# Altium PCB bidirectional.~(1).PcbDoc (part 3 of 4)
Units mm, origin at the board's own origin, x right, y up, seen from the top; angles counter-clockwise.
Board outline 190.5 x 127 mm, 6 copper layers (Top Layer, MidLayer1, MidLayer2, Mid-Layer 3, Mid-Layer 4, Bottom Layer), stack 2.997 mm thick; 416 components, 178 nets, 1084 pads, 2010 vias.
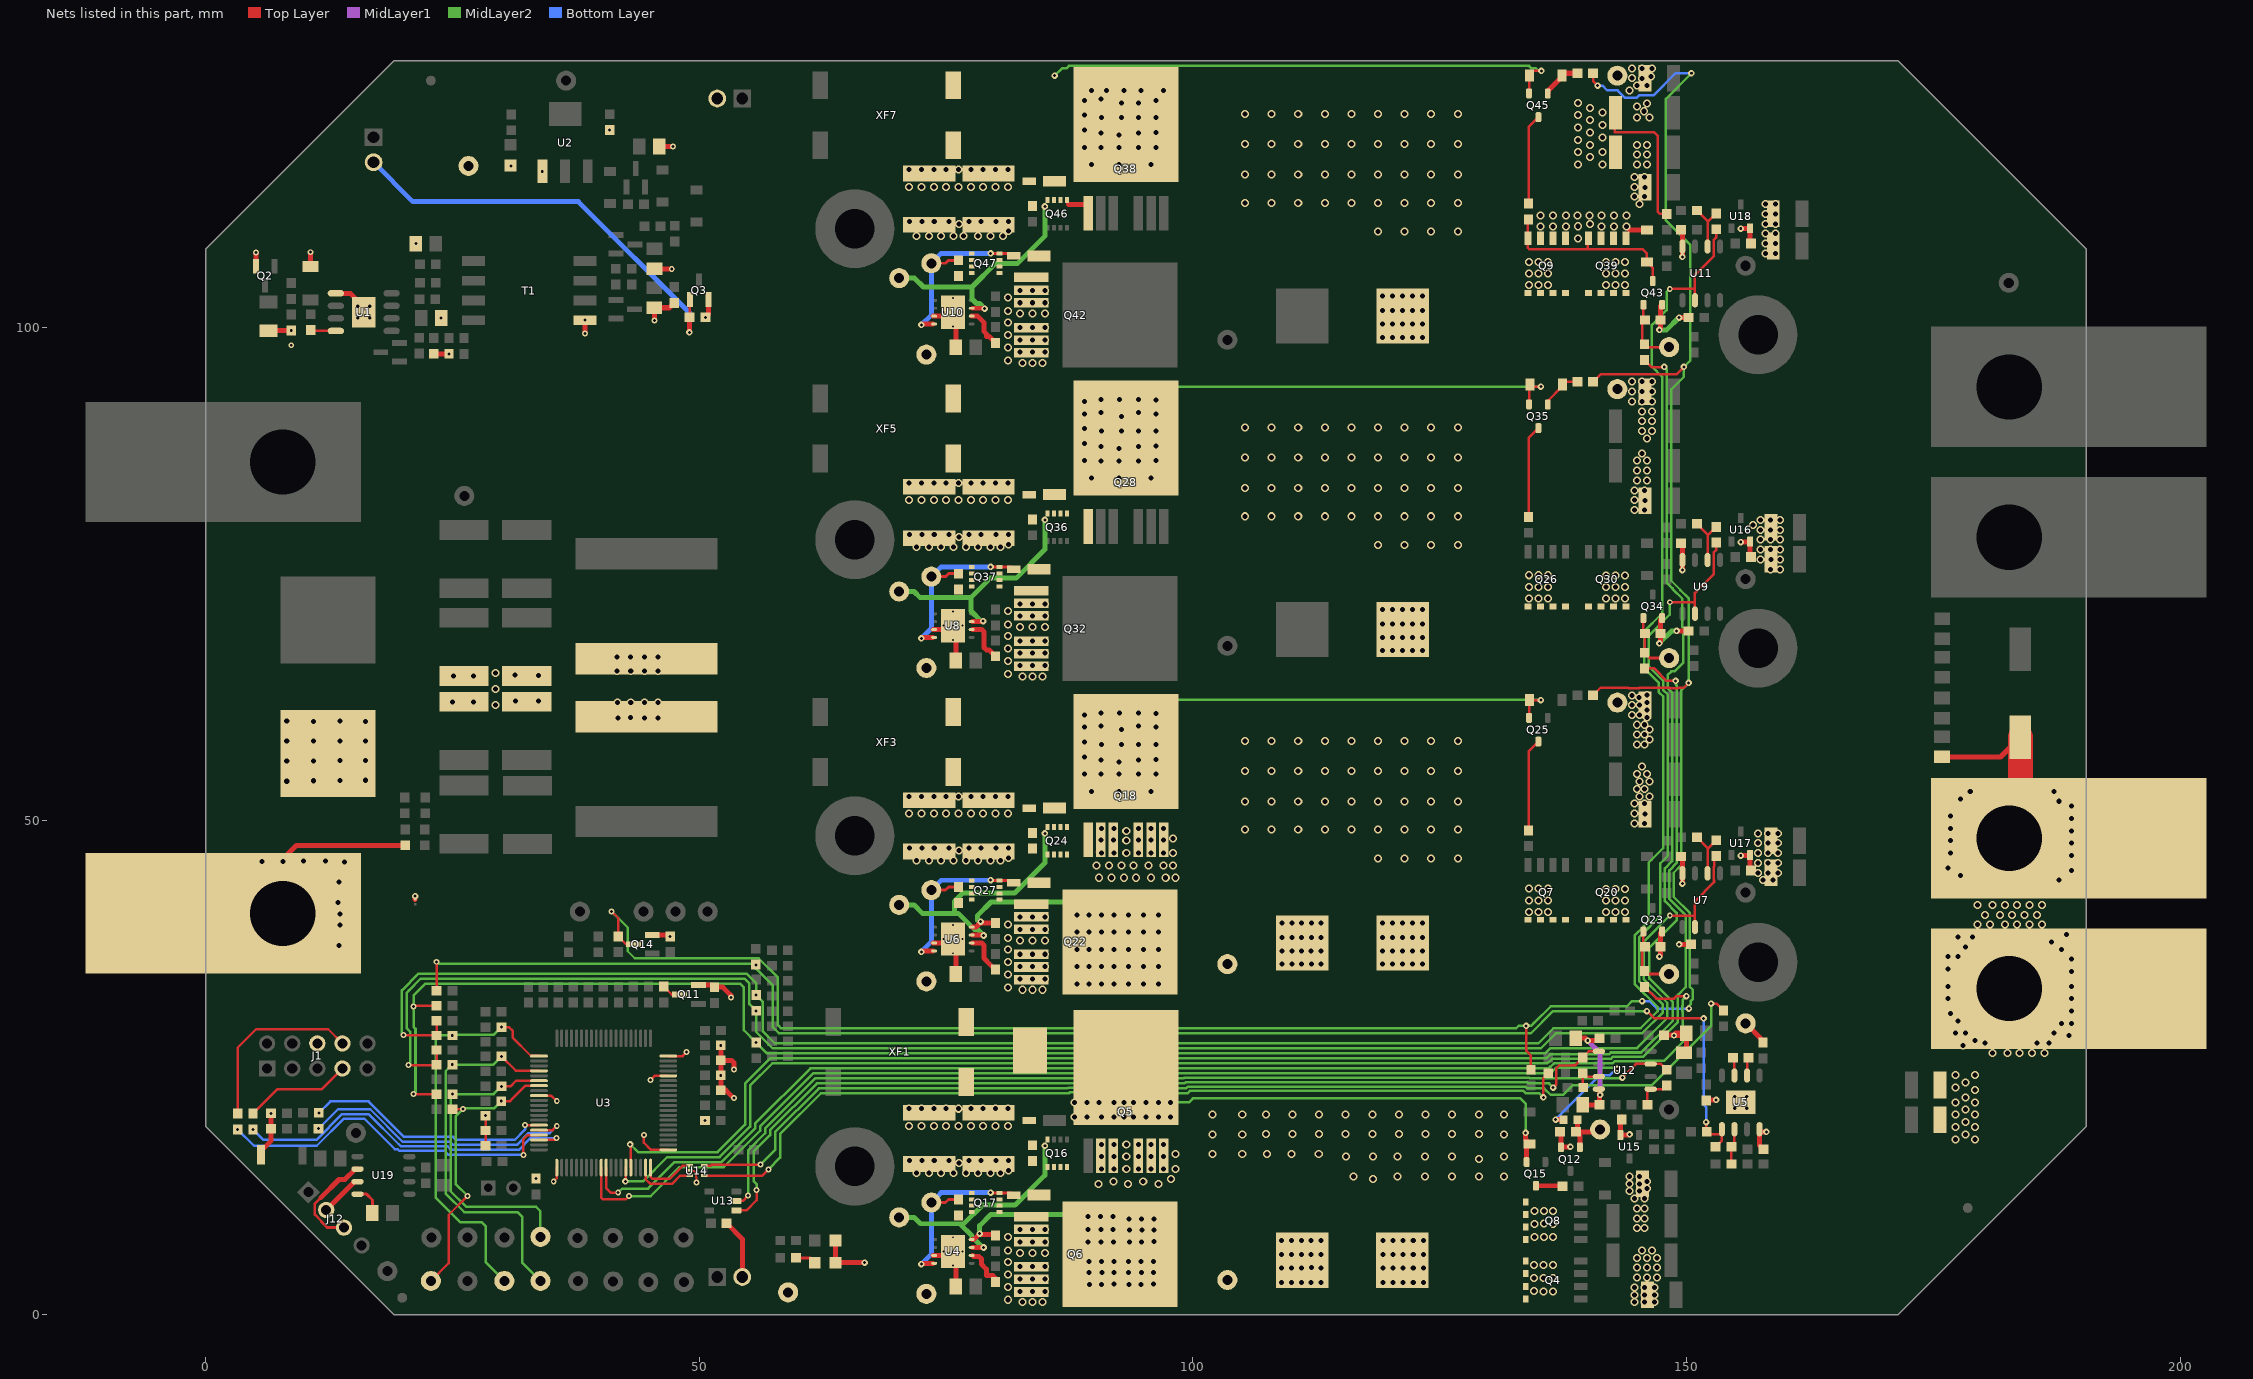
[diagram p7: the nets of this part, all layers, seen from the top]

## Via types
v1: diameter 0.813, hole 0.508, Top Layer to Bottom Layer, 1661 vias
v2: diameter 0.6, hole 0.3, Top Layer to Bottom Layer, 178 vias
v3: diameter 0.66, hole 0.3, Top Layer to Bottom Layer, 84 vias
v4: diameter 0.66, hole 0.3, Top Layer to Bottom Layer, tented both sides, 35 vias
v5: diameter 0.5, hole 0.2, Top Layer to Bottom Layer, 20 vias
v6: diameter 0.813, hole 0.508, Top Layer to Bottom Layer, tented both sides, 10 vias
v7: diameter 0.66, hole 0.33, Top Layer to Bottom Layer, tented top, 8 vias
v8: diameter 0.6, hole 0.3, Top Layer to Bottom Layer, tented both sides, 7 vias
v9: diameter 0.813, hole 0.508, Top Layer to Bottom Layer, tented top, 5 vias
v10: diameter 0.864, hole 0.406, Top Layer to Bottom Layer, 2 vias

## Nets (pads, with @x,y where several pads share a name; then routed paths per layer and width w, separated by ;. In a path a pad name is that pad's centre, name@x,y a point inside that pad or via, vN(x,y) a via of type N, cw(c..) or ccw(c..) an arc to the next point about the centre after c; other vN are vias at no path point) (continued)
NetD14_1: D14.1 Q9.4 Q39.4 Q43.3 R94.2 | length 19.4
  Top Layer w0.254: R94.2@134,110.95 133.939,110.889 Q9.4@133.939,109.041 133.939,108.068 134.092,107.916 140,107.916 ; Q39.4@140.086,109.041 140,108.955 140,107.916 ; Q43.3@146.588,104.7 146.588,106.024 D14.1@146,106.612 146,107.5 145.584,107.916 140,107.916
NetD14_2: D14.2 Q9.1 Q9.2 Q9.3 Q39.1 Q39.2 Q39.3 R90.1 R95.1 R103.1 | length 17.1
  Top Layer w0.25: R95.1@142.75,121.45 142.75,119.75 146.75,119.75 147.07,119.43 147.07,111.73 147.3,111.5 R103.1@148,111.5
  Top Layer w0.254: v1@135.209,111.091 v1@135.235,111.091
  Top Layer w0.508: v1(143.922,110.202) 144.236,109.887 D14.2@146,109.887
  other v1: 139,109 135.209,110.202 136.505,110.202 137.775,110.202 141.382,110.202 142.652,110.202 139,110.25 140.25,110.5 135.209,111.345 136.479,111.345 137.775,111.345 138.969,111.345 140.162,111.345 141.382,111.345 142.652,111.345 143.922,111.345 139,116.5 141.5,116.5 140.25,117.25 139,117.75 141.5,117.75 140.25,118.5 139,119 141.5,119.25 140.25,119.75 139,120.25 141.5,120.5 140.25,121 139,121.5 141.5,121.75 140.25,122.25 139,122.75
NetD15_2: D15.2 Q45.1 R101.1 | length 4.1
  Top Layer w0.508: Q45.1@135.95,123.7 135.95,123.95 137.388,125.388 D15.2@137.388,125.5 137.637,125.75 R101.1@138.95,125.75
NetD16_1: D16.1 R16.1 | length 2.1
  Top Layer w0.3: R16.1@59.8,5.75 61.2,5.75 D16.1@61.7,5.25
NetD18_2: D18.2 Q35.1 R82.1 | length 4.2
  Top Layer w0.254: Q35.1@135.95,92.2 135.95,92.562 137.388,94 137.887,94.5 R82.1@138.95,94.5
NetD19_1: D19.1 Q6.1 Q17.1 Q17.2 Q17.3 | length 0
  Top Layer w0.5: Q6.1@84.694,9.906 Q6.1@84.7,9.912
NetD20_1: D20.1 Q18.1 Q24.1 Q24.2 Q24.3
NetD21_1: D21.1 Q22.1 Q27.1 Q27.2 Q27.3
NetD22_1: D22.1 Q28.1 Q36.1 Q36.2 Q36.3 | length 0.9
  Top Layer w0.5: Q28.1@89.366,80.7 89.408,80.658 Q28.1@89.408,79.836
NetD23_1: D23.1 Q32.1 Q37.1 Q37.2 Q37.3
NetD24_1: D24.1 Q38.1 Q46.1 Q46.2 Q46.3 | length 2.7
  Top Layer w0.5: 87.4,112.45 89.05,112.45 89.408,112.092 Q38.1@89.408,111.586
NetD25_1: D25.1 Q42.1 Q47.1 Q47.2 Q47.3
NetJ1_7: J1.7 R26.1 | length 11
  Top Layer w0.254: R26.1@4.781,20.362 7.218,22.8 11.71,22.8 J1.7@13.84,24.93
NetJ1_8: J1.8 R24.1 | length 18.6
  Top Layer w0.254: R24.1@3.231,20.362 3.231,27.031 5.1,28.9 12.41,28.9 J1.8@13.84,27.47
NetJ12_2: J12.2 U19.7 | length 4.4
  Top Layer w0.5: J12.2@12.202,10.598 15.069,13.465 U19.7@15.375,13.465
NetJ12_3: J12.3 U19.6 | length 10.4
  Top Layer w0.25: 11.686,11.872 11.053,11.239 11.053,10.122 11.726,9.449
  Top Layer w0.3: 11.708,9.431 12.338,8.802 J12.3@13.998,8.802
  Top Layer w0.5: 11.686,11.872 13.5,13.686 14.086,13.686 15.135,14.735 U19.6@15.375,14.735
NetL1_2: L1.2 L2.1
  other v1: 41.758,60.452 44.425,60.452 45.796,60.452 43.028,60.477 41.707,62.027 43.053,62.027 44.425,62.027 45.796,62.027 41.656,65.176 43.053,65.176 44.425,65.176 45.796,65.176 41.656,66.599 43.028,66.599 44.425,66.599 45.796,66.599
NetL3_2: L3.2 Q4.5 Q4.6 Q4.7 Q4.8 Q8.5 Q8.6 Q8.7 Q8.8
  other v1: 135.535,2.358 136.5,2.358 134.57,2.384 119.25,3.25 120.291,3.25 121.307,3.25 122.323,3.25 123.339,3.25 134.57,3.679 135.535,3.679 136.5,3.679 119.275,4.698 120.291,4.698 121.307,4.698 122.323,4.698 123.339,4.698 134.57,5 135.535,5 136.5,5 119.275,6.069 120.291,6.069 121.307,6.069 122.323,6.069 123.339,6.069 119.275,7.492 120.291,7.492 121.307,7.492 122.323,7.492 123.339,7.492 136.5,9.179 135.56,9.205 134.62,10.5 135.56,10.5 136.5,10.5
  other v9: 134.62,7.858 135.56,7.858 136.5,7.858 134.62,9.179
NetL4_2: L4.2 Q7.5 Q7.6 Q7.7 Q7.8 Q20.5 Q20.6 Q20.7 Q20.8
  other v1: 119.211,35.5 120.227,35.5 121.243,35.5 122.234,35.5 123.25,35.5 119.211,36.846 120.227,36.846 121.243,36.846 122.234,36.846 123.25,36.846 119.211,38.218 120.227,38.218 121.243,38.218 122.234,38.218 123.25,38.218 119.211,39.666 120.227,39.666 121.243,39.666 122.234,39.666 123.25,39.666 134.066,40.784 135.032,40.784 142.804,40.784 143.769,40.784 134.066,41.952 135.032,41.952 135.997,41.952 141.839,41.952 142.804,41.952 143.769,41.952 141.839,43.12 142.804,43.12 143.769,43.12 134.066,43.146 135.032,43.146 135.997,43.146
  other v6: 135.997,40.784 141.839,40.784
NetL5_2: L5.2 Q26.5 Q26.6 Q26.7 Q26.8 Q30.5 Q30.6 Q30.7 Q30.8
  other v1: 119.211,67.25 120.227,67.25 121.243,67.25 122.234,67.25 123.25,67.25 119.211,68.596 120.227,68.596 121.243,68.596 122.234,68.596 123.25,68.596 119.211,69.968 120.227,69.968 121.243,69.968 122.234,69.968 123.25,69.968 119.211,71.416 120.227,71.416 121.243,71.416 122.234,71.416 123.25,71.416 134.066,72.534 135.032,72.534 142.804,72.534 143.769,72.534 134.066,73.702 135.032,73.702 135.997,73.702 141.839,73.702 142.804,73.702 143.769,73.702 141.839,74.87 142.804,74.87 143.769,74.87 134.066,74.896 135.032,74.896 135.997,74.896
  other v6: 135.997,72.534 141.839,72.534
NetL6_2: L6.2 Q9.5 Q9.6 Q9.7 Q9.8 Q39.5 Q39.6 Q39.7 Q39.8
  other v1: 119.211,99 120.227,99 121.243,99 122.234,99 123.25,99 119.211,100.346 120.227,100.346 121.243,100.346 122.234,100.346 123.25,100.346 119.211,101.718 120.227,101.718 121.243,101.718 122.234,101.718 123.25,101.718 119.211,103.166 120.227,103.166 121.243,103.166 122.234,103.166 123.25,103.166 134.066,104.284 135.032,104.284 142.804,104.284 143.769,104.284 134.066,105.452 135.032,105.452 135.997,105.452 141.839,105.452 142.804,105.452 143.769,105.452 141.839,106.62 142.804,106.62 143.769,106.62 134.066,106.646 135.032,106.646 135.997,106.646
  other v6: 135.997,104.284 141.839,104.284
NetQ11_3: Q11.3 R35.1 | length 1.9
  Top Layer w0.254: R35.1@46.406,33.223 47.206,32.423 Q11.3@48.006,32.423
NetQ15_3: Q15.3 R34.1 | length 2.7
  Top Layer w0.5: Q15.3@134.75,13.05 137.4,13.05 R34.1@137.45,13
NetQ25_3: Q25.3 R56.1 | length 9.4
  Top Layer w0.254: R56.1@134,49.05 134,57.05 Q25.3@135,58.05
NetQ35_3: Q35.3 R75.1 | length 9.4
  Top Layer w0.254: R75.1@134,80.8 134,88.8 Q35.3@135,89.8
NetQ45_3: Q45.3 R94.1 | length 9.3
  Top Layer w0.254: R94.1@134,112.55 134,120.3 Q45.3@135,121.3 ; Q45.3@134.875,121.425 Q45.3@135,121.55
NetR4_2: R4.2 U1.4 | length 2.5
  Top Layer w0.254: R4.2@10.706,99.644 U1.4@13.208,99.644
NetR20_2: R20.2 U4.2 | length 4.4
  Top Layer w0.5: U4.2@77.686,5.993 77.783,5.896 78.316,5.896 78.579,5.633 78.579,5.099 79.076,4.603 79.076,3.939 79.74,3.939 80,3.679 R20.2@80,3.288
NetR21_2: R21.2 U6.2 | length 4.2
  Top Layer w0.5: U6.2@77.686,37.643 78.455,37.643 78.477,37.621 78.629,37.621 78.838,37.412 78.838,36.1 79.076,35.862 79.076,35.852 79.99,34.938 R21.2@80,34.938
NetR22_2: R22.2 U8.2 | length 4.4
  Top Layer w0.5: U8.2@77.686,69.393 78.607,69.393 78.838,69.162 78.838,67.577 79.076,67.339 79.349,67.339 R22.2@80,66.688
NetR23_2: R23.2 U10.2 | length 4.2
  Top Layer w0.5: U10.2@77.592,101.142 78.196,101.142 78.859,100.479 78.859,99.579 79.076,99.362 79.076,99.089 79.349,99.089 R23.2@80,98.438
NetR43_2: R43.2@13.616,15.8 U19.5 | length 1.8
  Top Layer w0.5: R43.2@13.616,15.8 13.821,16.005 U19.5@15.375,16.005
NetR43_2: R43.2@154.55,15.25 R44.1 U5.2 | length 3.4
  Top Layer w0.254: R43.2@154.55,15.25 154.55,16.75 154.865,17.065 U5.2@154.865,18.525
NetR44_2: R44.2 R45.1 R47.2 R120.1 U5.1 | length 154
  Top Layer w0.254: R45.1@23.381,32.791 23.381,35.725 v2(23.393,35.738) ; v3(146,30.75) 146.75,30 v3(151.75,30) ; v3(152,19.5) 152,18.3 152.05,18.25 153.32,18.25 U5.1@153.595,18.525 ; R44.2@152.95,16.75 R44.2@153.075,16.875 ; R44.2@152.95,17 153.595,17.645 U5.1@153.595,18.525 ; U5.1@153.595,18.775 U5.1@153.595,18.525
  MidLayer2 w0.254: v2(23.393,35.738) 23.571,35.56 55.575,35.56 v2(55.728,35.408) 55.728,35.048 57.455,33.321 57.455,29.105 58.061,28.499 134.25,28.499 136.501,30.75 v3(146,30.75)
  Bottom Layer w0.254: v3(151.75,30) 151.75,21.25 152,21 v3(152,19.5)
NetR60_1: R60.1 R62.2 R64.1 R66.2 U7.6 | length 172.4
  Top Layer w0.254: v2(21.057,22.327) R60.1@23.381,22.327 ; v2(21.057,31.191) 21.158,31.293 R64.1@23.381,31.293 ; v2(148.311,40.411) 150.761,40.411 150.865,40.308 ; U7.6@150.865,39.25 150.865,40.308 ; R62.2@153,46.45 152.8,46.25 152.8,45.405 152.779,45.384 152.779,44.016 152.8,43.995 152.8,43.8 150.865,41.865 150.865,40.308
  MidLayer2 w0.254: v2(21.057,22.327) 21.247,22.517 21.247,28.943 21.057,29.134 v2(21.057,31.191) 21.057,32.309 22.276,33.528 54.127,33.528 54.508,33.147 54.508,28.803 v2(55.753,27.559) 56.845,26.467 135.687,26.467 136.22,27 145,27 148.057,30.057 148.057,31.584 145.656,33.985 145.656,37.757 v2(148.311,40.411)
NetR61_2: R61.2 R62.1 U7.2 | length 5.3
  Top Layer w0.25: R61.2@151.05,48.35 152.135,47.265 ; U7.2@152.135,44.7 152.135,47.265 ; R62.1@153,48.05 152.215,47.265 152.135,47.265
NetR79_1: R79.1 R81.2 R83.1 R85.2 U9.6 | length 203
  Top Layer w0.254: v2@20.549,25.273 R79.1@23.381,25.273 ; R79.1@23.381,25.298 R83.1@23.381,26.797 ; v2(148.311,72.161) 150.761,72.161 150.865,72.058 ; U9.6@150.865,71 150.865,72.058 ; R81.2@152.8,78 R81.2@153,78.2 153,77.45 152.779,77.229 152.779,75.029 150.865,73.115 150.865,72.058
  MidLayer2 w0.254: v2(20.549,25.298) 20.701,25.451 20.701,28.651 20.371,28.981 20.371,32.61 20.574,32.814 20.574,32.831 21.779,34.036 54.585,34.036 55.067,33.553 55.067,31.458 v2(55.753,30.772) 55.753,28.651 57.429,26.975 135.25,26.975 136.775,28.5 145.5,28.5 147.604,30.604 147.604,31.396 145.203,33.797 145.203,38.202 146.135,39.134 ; 146.15,39.149 146.135,39.134 ; 146.614,39.642 146.135,39.164 146.135,39.134 ; 146.635,39.642 147.358,40.365 147.358,45.723 148.104,46.469 148.104,62.812 147.641,63.276 147.641,64.209 146.156,65.693 146.156,68.75 148.311,70.905 v2(148.311,72.161)
NetR80_2: R80.2 R81.1 U9.2 | length 5.3
  Top Layer w0.25: R80.2@151.05,80.1 152.135,79.015 ; U9.2@152.135,76.45 152.135,79.015 ; R81.1@153,79.8 152.215,79.015 152.135,79.015
NetR98_1: R98.1 R100.2 R102.1 R104.2 U11.6 | length 233.2
  Top Layer w0.254: v2@20.041,28.27 R98.1@23.381,28.27 ; R98.1@23.406,28.143 R102.1@23.406,29.642 ; v2(148.311,103.911) 150.761,103.911 150.865,103.808 ; U11.6@150.865,102.75 150.865,103.808 ; R100.2@152.8,109.75 R100.2@153,109.95 153,109.105 152.779,108.884 152.779,107.229 150.865,105.315 150.865,103.808
  MidLayer2 w0.254: v2(20.015,28.321) 19.863,28.473 19.863,32.838 21.568,34.544 54.795,34.544 55.753,33.586 v2(55.753,32.36) 56.439,31.674 56.439,28.684 57.64,27.483 135,27.483 136.517,29 145.346,29 147.096,30.75 147.096,31.154 144.75,33.5 144.75,38.389 145.682,39.321 145.682,39.351 146.203,39.872 146.203,40.188 146.182,40.209 146.182,45.781 147.651,47.25 147.651,62.625 147.188,63.088 147.188,64.021 145.703,65.505 145.703,69.203 147.547,71.047 147.547,94.998 146.5,96.045 146.5,100.25 148,101.75 148,103.601 v2(148.311,103.911)
NetR99_2: R99.2 R100.1 U11.2 | length 5.3
  Top Layer w0.25: R99.2@151.05,111.85 152.135,110.765 ; U11.2@152.135,108.2 152.135,110.765 ; R100.1@153,111.55 152.215,110.765 152.135,110.765
NetR109_1: R109.1 U14.4 | length 93.8
  Top Layer w0.254: U14.4@50.499,14.08 56.385,14.08 57,14.695 v2(57,14.7) ; v3(135.5,22) 135.5,23.95 R109.1@136,24.45
  MidLayer2 w0.254: v2(57,14.7) 58.191,15.891 58.191,18.291 62.303,22.403 87.441,22.403 87.572,22.533 88.428,22.533 88.559,22.403 88.691,22.403 88.822,22.533 89.678,22.533 89.809,22.403 89.941,22.403 90.072,22.533 90.928,22.533 91.059,22.403 91.441,22.403 91.572,22.533 92.428,22.533 92.5,22.461 92.572,22.533 93.428,22.533 93.5,22.461 93.572,22.533 94.428,22.533 94.559,22.403 94.691,22.403 94.822,22.533 95.678,22.533 95.809,22.403 95.941,22.403 96.072,22.533 96.928,22.533 97.059,22.403 97.191,22.403 97.322,22.533 98.178,22.533 98.309,22.403 99.442,22.403 99.688,22.649 133.486,22.649 133.732,22.403 135.097,22.403 v3(135.5,22)
NetR111_2: R111.2 R112.2 U12.3 | length 2.7
  Top Layer w0.254: 139.5,23.874 139.5,23.05 R111.2@139.55,23 ; R112.2@139.5,24.45 139.835,24.115 U12.3@141.125,24.115
NetR112_1: R112.1 U12.1 U13.1 | length 99.2
  Top Layer w0.2: 137.134,25.232 137.151,25.249 137.801,25.249 137.802,25.25 138.356,25.25
  Top Layer w0.25: v3(136.5,23) 136.799,23.299 136.799,24.932 137.117,25.25 ; R112.1@139.5,26.05 140.105,26.655 U12.1@141.125,26.655
  Top Layer w0.254: U13.1@53.618,10.556 54.778,10.556 55.8,11.579 v2(55.8,12.6) ; 138.356,25.25 138.7,25.25 R112.1@139.5,26.05
  MidLayer2 w0.25: 134.75,23.419 136.081,23.419 v3(136.5,23)
  MidLayer2 w0.254: v2(55.8,12.6) 55.8,13.212 55.5,13.512 55.5,16.5 57.175,18.175 57.175,18.675 61.919,23.419 87.176,23.419 87.197,23.439 88.803,23.439 90.053,23.439 91.303,23.439 92.803,23.439 93.803,23.439 94.803,23.439 96.053,23.439 97.303,23.439 98.553,23.439 98.574,23.419 99.176,23.419 99.312,23.555 133.862,23.555 133.998,23.419 134.75,23.419
NetR113_1: R113.1 U14.6 | length 113.6
  Top Layer w0.254: U14.6@50.499,15.08 51.173,15.08 51.293,15.2 v2(56.2,15.2) ; v3(152.5,31.5) 153.05,31.5 R113.1@153.75,30.8
  MidLayer2 w0.254: v2(56.2,15.2) 57.683,16.683 57.683,18.483 62.111,22.911 87.309,22.911 87.384,22.986 88.616,22.986 88.625,22.977 88.634,22.986 89.866,22.986 89.875,22.977 89.884,22.986 91.116,22.986 91.191,22.911 91.309,22.911 91.384,22.986 92.616,22.986 93.616,22.986 94.616,22.986 94.625,22.977 94.634,22.986 95.866,22.986 95.875,22.977 95.884,22.986 97.116,22.986 97.125,22.977 97.134,22.986 98.366,22.986 98.441,22.911 99.309,22.911 99.5,23.102 133.674,23.102 133.865,22.911 135.589,22.911 136.25,22.25 137.5,22.25 138.5,23.25 146.5,23.25 152.5,29.25 v3(152.5,31.5)
NetR115_2: R115.2 R116.2 U12.5 | length 3.5
  Top Layer w0.254: R115.2@146.05,21.25 146.05,22.52 U12.5@146.375,22.845 147.645,22.845 R116.2@148,23.2
NetR116_1: R116.1 U12.7 U13.2 | length 103.4
  Top Layer w0.254: U13.2@53.618,11.506 54.407,11.506 v2(54.94,12.04) ; v3(143.5,24) 144.885,25.385 U12.7@146.375,25.385 147.415,25.385 R116.1@148,24.8
  MidLayer2 w0.254: v2(54.94,12.04) 54.94,16.64 56.667,18.367 56.667,18.867 61.727,23.927 99.044,23.927 99.125,24.008 134.049,24.008 134.13,23.927 143.427,23.927 v3(143.5,24)
NetR121_1: R121.1 U5.6 | length 1.8
  Top Layer w0.254: U5.6@156.135,24.225 156.135,25.835 R121.1@156.3,26
NetR121_2: R121.2 U5.7 | length 1.8
  Top Layer w0.254: R121.2@154.7,26 154.865,25.835 U5.7@154.865,24.225
NetR124_2: R124.2 U3.30 | length 121.1
  Top Layer w0.254: U3.30@40.06,14.888 40.06,11.86 40.261,11.659 42.545,11.659 v2(42.875,11.989)
  Top Layer w0.508: v3(136.75,19.75) R124.2@137.55,19.75
  MidLayer2 w0.254: v2(42.875,11.989) 45.054,11.989 48,14.935 52.476,14.935 56.159,18.619 56.159,19.059 61.535,24.435 98.911,24.435 98.937,24.461 134.237,24.461 134.263,24.435 136.162,24.435 136.382,24.655 136.437,24.655 136.783,25 142.713,25 142.813,24.9 v3(143,24.9)
  Bottom Layer w0.25: v3(136.75,19.75) 141.25,24.25
  Bottom Layer w0.254: 141.25,24.25 142.25,24.25 142.9,24.9 v3(143,24.9)
NetR125_2: R125.2 U3.31 | length 127.6
  Top Layer w0.254: U3.31@40.56,14.888 40.56,12.806 41.021,12.344 v2(41.783,12.344) ; R125.2@145.75,33.2 146.95,32 148.75,32 149,32.25 v3(150,32.25)
  MidLayer2 w0.254: v2(41.783,12.344) 42.189,12.75 44.807,12.75 47.5,15.443 52.243,15.443 55.651,18.851 55.651,19.351 61.243,24.943 136.025,24.943 136.08,24.998 136.084,24.998 136.194,25.108 136.25,25.108 136.595,25.453 142.525,25.453 142.713,25.641 145.822,25.641 145.886,25.705 147.705,25.705 149.636,27.636 149.636,28.691 149.615,28.712 149.615,30.707 149.594,30.728 149.594,31.272 149.615,31.293 149.615,31.865 v3(150,32.25)
NetR126_2: R126.2 U3.35 | length 156.8
  Top Layer w0.254: v4(42.5,13.5) 42.56,13.56 U3.35@42.56,14.888 ; R126.2@145.75,65.45 146.75,65.45 148,64.2 v3(148.9,64.2)
  MidLayer2 w0.254: v4(42.5,13.5) 44.299,13.5 46.75,15.951 52.051,15.951 55.143,19.043 55.143,23.208 57.386,25.451 135.897,25.451 136.007,25.561 136.062,25.561 136.407,25.906 142.337,25.906 142.525,26.094 145.594,26.094 149.128,29.628 149.128,32.378 149.906,33.156 149.906,40.474 148.264,42.116 148.264,45 149.01,45.746 149.01,63.74 148.9,63.85 v3(148.9,64.2)
NetR127_2: R127.2 U3.36 | length 189.6
  Top Layer w0.254: v4(43,17.25) 43.06,17.19 U3.36@43.06,14.888 ; R127.2@145.75,96.7 146.475,95.975 147.725,95.975 v3(147.75,96)
  MidLayer2 w0.254: v4(43,17.25) 43.791,16.459 51.859,16.459 54.635,19.235 54.635,23.419 57.176,25.959 135.764,25.959 135.819,26.014 135.874,26.014 136.22,26.359 142.15,26.359 142.338,26.547 145.406,26.547 148.62,29.761 148.62,31.661 146.25,34.031 146.25,37.183 148.996,39.93 148.996,40.695 147.811,41.881 147.811,45.188 148.557,45.934 148.557,63 148.094,63.463 148.094,63.978 148.094,64.522 ; v3(147.75,96) 148,95.75 148,74.16 148.594,73.566 148.594,73.515 149.592,72.517 149.592,69.65 149.656,69.586 149.656,66.008 148.806,65.158 148.48,65.158 148.094,64.772 148.094,64.522
NetR135_1: R135.1 U19.8 | length 3.1
  Top Layer w0.3: U19.8@15.375,12.195 16.305,12.195 16.884,11.616 R135.1@16.884,10.3
ON/OFF: J11.2 Q3.1 R12.2 | length 43.7
  Top Layer w0.254: R12.2@49.009,101.016 49.009,102.807 Q3.1@49.037,102.834
  Top Layer w0.5: v3(49,99.5) 49.009,99.509 R12.2@49.009,101.016
  Bottom Layer w0.5: J11.2@17,116.73 20.98,112.75 37.75,112.75 49,101.5 v3(49,99.5)
ORING_CTR: Q14.3 R33.1 R41.2 R63.2 R82.2 R101.2 | length 261.7
  Top Layer w0.254: v2(41.123,40.818) 41.783,40.157 R33.1@41.783,38.316 42.583,37.516 Q14.3@43.322,37.516 ; v3(133.75,29.25) 133.75,26.75 134.25,26.25 R41.2@134.25,24.8 ; R63.2@140.55,62.75 141.3,63.5 144.1,63.5 144.16,63.44 145.182,63.44 145.242,63.5 148.322,63.5 148.396,63.426 149.104,63.426 149.178,63.5 149.75,63.5 150.22,63.97 v3(150.22,64) ; R82.2@140.55,94.5 141.3,95.25 149,95.25 v3(149.75,96) ; R101.2@140.55,125.75 140.55,124.95 v3(141,124.5)
  MidLayer2 w0.254: v2(41.123,40.818) 42.748,39.192 42.748,36.805 43.459,36.093 56.012,36.093 57.963,34.142 57.963,29.315 58.271,29.007 132.757,29.007 133,29.25 v3(133.75,29.25) 134.25,29.25 134.547,29.547 134.577,29.547 136.25,31.22 136.25,31.25 144,31.25 144.5,31.75 v3(145.5,31.75) ; v3(150.25,31) 150.25,31.257 150.453,31.46 150.453,31.775 150.656,31.978 150.656,32.906 150.359,33.203 150.359,40.662 148.717,42.304 148.717,44.754 149.463,45.5 149.463,63.213 150.25,64 150.25,72.521 149.373,73.398 149.373,73.428 148.462,74.339 148.462,93.712 149.75,95 v3(149.75,96) 150.28,96.53 150.28,96.534 150.406,96.66 150.406,108.344 147.909,110.841 147.909,123.159 v3(150.5,125.75)
  Bottom Layer w0.254: v3(141,124.5) 141.5,124.5 141.98,124.02 143.02,124.02 143.79,123.25 144.96,123.25 145.21,123.5 146.65,123.5 148.9,125.75 v3(150.5,125.75) ; v3(145.5,31.75) 146.25,31.75 147,31 v3(150.25,31)
PGND: C2.2 C6.2 C7.2 C8.2 C9.2 C10.2 C11.2 C12.2 C13.2 C14.2 C15.2 C18.2 C19.2 C20.2 C21.2 C23.2 C24.2 C28.2 C29.1 C30.2 C31.1 C32.2 C33.2 C34.2 C35.2 C36.2 C42.2 C44.2 C47.2 C48.2 C49.2 C50.2 C52.2 C53.2 C54.2 C56.2 C57.2 C58.2 C61.2 C64.2 C65.2 C66.2 C67.2 C70.2 C73.2 C74.2 C75.2 C76.2 C79.2 C82.2 C83.2 C84.2 C85.2 C88.2 C91.2 C93.1 C95.1 C97.1 C99.2 C100.2 C101.2 C102.2 C104.2 C105.2 C106.1 C107.2 C108.1 C109.1 C110.2 C111.2 C112.1 C113.2 C116.2 C117.2 C118.2 C119.2 C120.2 C121.2 C122.2 C123.2 D2.2 D7.2 D16.2 J1.6 J5.1 J6.1 J7.1 J8.2 J9.2 NT1.2 Q2.2 Q3.2 Q6.2 Q6.3 Q6.5 Q6.6 Q6.7 Q11.2 Q12.2 Q14.2 Q17.5 Q17.6 Q17.7 Q17.8 Q22.2 Q22.3 Q22.5 Q22.6 Q22.7 Q23.2 Q27.5 Q27.6 Q27.7 Q27.8 Q32.2 Q32.3 Q32.5 Q32.6 Q32.7 Q34.2 Q37.5 Q37.6 Q37.7 Q37.8 Q42.2 Q42.3 Q42.5 Q42.6 Q42.7 Q43.2 Q47.5 Q47.6 Q47.7 Q47.8 R7.1 R10.1 R11.1 R12.1 R38.1 R39.1 R40.1 R59.1 R78.1 R97.1 R118.1 S1.1 T1.1 TP1.1 TP17.1 TP23.1 TP24.1 TP31.1 TP36.1 TP43.1 TP44.1 TP55.1 TP58.1 U1.1 U1.9 U2.1 U3.9 U3.21 U3.41 U3.56 U3.60 U4.7 U4.9 U5.4 U5.9 U6.7 U6.9 U7.4 U8.7 U8.9 U9.4 U10.7 U10.9 U11.4 U12.4 U14.2 U15.2 U16.2 U17.2 U18.2 | length 190.4
  Top Layer w0.2: U14.2@49.019,14.58 49.07,14.529 49.477,14.529 49.653,14.353 49.653,13.946 49.708,13.89 v2@49.708,13.411
  Top Layer w0.254: v2(28.334,20.142) 28.347,20.13 C20.2@28.347,18.644 C28.2@28.347,17.12 ; U3.9@33.76,22.188 34.988,22.188 v2(35.56,21.615) ; v2(35.25,13.5) 35.56,13.81 U3.21@35.56,14.888 ; v2(44.374,18.186) 44.374,17.424 45.111,16.688 U3.41@46.86,16.688 ; v2(45.06,23.774) 45.473,24.188 U3.56@46.86,24.188 ; U3.60@46.86,26.188 48.311,26.188 v2(48.717,26.594) ; v2@49.708,13.411 v2(49.733,13.386)
  Top Layer w0.508: J5.1@2.286,40.64 9.182,47.536 C57.2@20.193,47.536 ; Q2.2@5.07,106.208 v2(5.07,107.584) ; S1.1@5.6,16.2 5.6,16.6 6.622,17.622 C14.2@6.622,18.826 C15.2@6.622,20.401 ; C7.2@6.35,99.667 8.621,99.667 v2(8.661,99.708) ; C6.2@10.617,106.17 v2(10.617,107.62) ; U1.1@13.177,103.454 14.64,103.454 U1.9@15.674,102.421 ; NT1.2@21.2,42.054 v4(21.2,42.4) ; R11.1@23.114,97.333 C10.2@24.638,97.333 ; v2(38.416,99.404) v2(38.416,100.734) ; Q14.2@45.222,38.466 46.916,38.466 R38.1@47.066,38.316 ; v2(45.441,100.711) C8.2@45.441,101.994 46.977,101.994 R10.1@47.473,102.489 ; C2.2@45.466,105.931 v2(47.206,105.931) ; C12.2@45.949,118.339 v2(47.346,118.339) ; Q11.2@49.906,33.373 51.323,33.373 R40.1@51.537,33.16 52.388,33.16 53.188,32.36 v2(53.188,32.131) ; v2(50.609,101.016) 50.937,101.344 Q3.2@50.937,102.834 ; v2(52.172,27.28) C19.2@52.172,25.756 ; C31.1@52.768,9.246 54.356,7.658 J9.2@54.356,3.81 ; v2(53.492,21.92) 52.68,22.733 C23.2@52.172,22.733 v2(52.172,24.232) C19.2@52.172,25.756 ; v2(53.492,24.841) 53.492,25.527 53.264,25.756 C19.2@52.172,25.756 ; D2.2@63.8,7.5 D16.2@63.8,5.25 v4(66.75,5.25) ; U4.7@73.698,5.993 75.293,5.993 v5(75.692,6.392) 75.997,6.087 C61.2@75.997,3.072 ; U6.7@73.698,37.643 75.293,37.643 v5(75.692,38.042) 75.997,37.737 C70.2@75.997,34.722 ; U8.7@73.698,69.393 75.293,69.393 v5(75.692,69.792) 75.997,69.487 C79.2@75.997,66.472 ; U10.7@73.698,101.143 75.293,101.143 v5(75.692,101.542) 75.997,101.237 C88.2@75.997,98.222 ; C107.2@137.2,18.5 137.3,18.4 137.3,17.539 ; Q12.2@137.3,16.95 138.2,16.95 v3(138.25,17) ; C99.2@138.766,28 139.75,28 v3(140,27.75) 140.95,27.75 C105.2@141.2,28 ; C100.2@139.516,21.25 C33.2@141.2,21.25 v3@141.2,22.2 ; U12.4@141.125,22.845 141.25,22.72 v3(141.25,22.25) ; C106.1@143.45,20 143.3,19.85 U15.2@143.3,18.2 144.2,18.2 v3(144.25,18.25) ; v3(147.25,36.25) 147.388,36.388 C111.2@147.388,37.25 147.388,38.65 Q23.2@147.538,38.8 ; v3(147.25,68) 147.388,68.138 C110.2@147.388,69 147.388,70.4 Q34.2@147.538,70.55 ; v3(147.25,99.75) 147.388,99.888 C113.2@147.388,100.75 147.388,102.15 Q43.2@147.538,102.3 ; C29.1@147.744,28.313 148.687,28.313 148.875,28.5 C101.2@149.984,28.5 ; v2(148.75,28.25) 149.734,28.25 C101.2@149.984,28.5 ; v4(149,69.25) C93.1@150.2,69.25 ; v3(149.25,37.5) C95.1@150.45,37.5 ; v4(149.25,101) C97.1@150.2,101 ; C34.2@149.45,46.4 149.595,46.255 U7.4@149.595,44.7 v3(149.595,43.655) ; C35.2@149.45,78.15 149.595,78.005 U9.4@149.595,76.45 v3(149.595,75.405) ; C36.2@149.45,109.9 149.595,109.755 U11.4@149.595,108.2 v3(149.595,107.155) ; C102.2@149.75,26.516 149.984,26.75 C101.2@149.984,28.5 ; C91.2@152,21.7 152.05,21.75 v3(153,21.75) ; v3(155.5,46.5) 156.4,46.5 U17.2@156.45,46.55 156.45,45.1 C109.1@156.55,45 ; v3(155.5,78.25) 156.4,78.25 U16.2@156.45,78.3 156.45,76.85 C108.1@156.55,76.75 ; v3(155.5,110) 156.4,110 U18.2@156.45,110.05 156.45,108.6 C112.1@156.55,108.5 ; TP24.1@156,29.5 157.75,27.75 C104.2@157.75,27.55 ; C32.2@157.8,16.75 157.405,17.145 157.405,18.5 v3(158.1,18.5) ; C58.2@175.895,56.49 181.818,56.49 C48.2@183.82,58.491
  Top Layer w2.54: C48.2@183.82,58.491 183.82,51.638 J7.1@187.198,48.26
  MidLayer1 w0.508: v3(140,27.75) 141.25,26.5 v3(141.25,22.25)
  MidLayer2 w0.508: v3(147.25,68) 148.5,69.25 v4(149,69.25) ; v3(147.25,99.75) 148,99.75 v4(149.25,101)
  other v1: 82.75,1.25 83.75,1.25 84.75,1.25 144.75,1.25 145.75,1.25 146.75,1.25 81.25,1.5 144.75,2 145.75,2 146.75,2 82.5,2.346 83.75,2.346 85,2.346 144.75,2.75 145.75,2.75 146.75,2.75 81.28,2.794 82.5,3.596 83.75,3.596 85,3.596 146,3.75 147,3.75 81.28,4.064 145,4.75 146,4.75 147,4.75 82.5,4.846 83.75,4.846 85,4.846 81.28,5.334 145,5.75 146,5.75 147,5.75 82.5,6.25 83.75,6.25 85,6.25 81.25,6.5 145.5,6.5 146.5,6.5 82.5,7.346 83.75,7.346 85,7.346 81.28,7.874 82.5,8.596 83.75,8.596 85,8.596 145,8.75 145.75,8.75 145,9.75 145.75,9.75 145,10.75 145.75,10.75 144.75,11.75 145.75,11.75 144.25,12.5 145.25,12.5 146,12.75 144.25,13.25 145.25,13.25 146,13.5 118.25,13.75 116.25,14 120.75,14 123.5,14 126.25,14 129,14 131.5,14 144.25,14 145.25,14 72,14.35 73.25,14.35 74.5,14.35 75.75,14.35 77,14.35 78.25,14.35 79.5,14.35 80.5,14.35 81.298,14.6 76.298,15.35 71.298,15.6 72.548,15.6 73.798,15.6 75.298,15.6 77.298,15.6 78.548,15.6 80.048,15.6 81.298,15.6 129,15.75 115.5,16 118.25,16 120.75,16 123.5,16 126.25,16 131.5,16 102,16.25 105,16.25 107.5,16.25 110,16.25 112.75,16.25 177.25,17.75 179.25,17.75 102,18.25 105,18.25 107.403,18.269 110.096,18.269 112.788,18.269 115.48,18.269 118.173,18.269 120.865,18.269 123.558,18.269 126.25,18.269 128.968,18.269 131.5,18.25 178.25,18.25 177.25,19 179.25,19 178.25,19.5 102,20.25 105,20.25 107.403,20.25 110.096,20.25 112.788,20.25 115.48,20.25 118.173,20.25 120.865,20.25 123.558,20.25 126.25,20.25 128.968,20.25 131.5,20.25 177.25,20.25 179.25,20.25 178.25,20.75 177.25,21.5 179.25,21.5 178.25,22 179.25,22.75 177.25,23 178.25,23.5 177.25,24.25 179.25,24.25 181,26.5 182.5,26.5 183.75,26.5 185,26.5 186.25,26.5 178,27.25 180.25,27.5 185.5,27.5 186.75,27.5 179.25,27.75 188.75,28.25 177.25,28.5 178.25,28.5 187.25,28.5 188,29.5 189,29.5 177.5,29.75 176.75,30.5 189,30.75 176.5,32 189,32 82.75,32.904 83.75,32.904 84.75,32.904 81.25,33.154 176.5,33.25 189,33.25 82.5,34 83.75,34 85,34 81.28,34.448 189,34.75 176.5,35 82.5,35.25 83.75,35.25 85,35.25 81.28,35.718 189,36 176.5,36.25 177.5,36.25 82.5,36.5 83.75,36.5 85,36.5 81.28,36.988 188,37 178.25,37.25 13.513,37.363 187,37.75 82.5,37.904 83.75,37.904 85,37.904 81.25,38.154 177.5,38.25 179,38.25 188.5,38.5 82.5,39 83.75,39 85,39 13.589,39.446 179.5,39.5 180.75,39.5 182.25,39.5 183.5,39.5 184.75,39.5 186,39.5 81.28,39.528 82.5,40.25 83.75,40.25 85,40.25 180.25,40.5 181.75,40.5 183,40.5 184.25,40.5 185.5,40.5 13.589,40.589 179.5,41.5 181,41.5 182.25,41.5 183.5,41.5 184.75,41.5 186,41.5 13.411,41.732 13.513,43.84 157.75,44 158.75,44 187.75,44 177.75,44.5 157.25,44.75 158.25,44.75 159.25,44.75 189,45 176.5,45.25 157.25,45.75 158.25,45.75 159.25,45.75 14.046,45.847 5.69,45.898 7.823,45.898 9.881,45.949 12.141,45.949 72,46 73.25,46 74.5,46 75.75,46 77,46 78.25,46 79.5,46 80.5,46 118.75,46.2 121.442,46.2 124.135,46.2 126.853,46.2 81.298,46.25 189,46.5 157.25,46.75 158.25,46.75 159.25,46.75 176.75,46.75 76.298,47 71.298,47.25 72.548,47.25 73.798,47.25 75.298,47.25 77.298,47.25 78.548,47.25 80.048,47.25 81.298,47.25 157.25,47.75 158.25,47.75 159.25,47.75 189,47.75 176.75,48 157.25,48.75 158.25,48.75 159.25,48.75 189,49 105.288,49.121 107.98,49.121 110.673,49.121 113.365,49.121 116.058,49.121 118.75,49.121 121.442,49.121 124.135,49.121 126.853,49.121 176.75,49.25 144.75,49.75 145.75,49.75 189,50.25 176.75,50.5 145.8,50.7 144.75,50.75 189,51.5 144.75,51.75 145.75,51.75 105.288,51.991 107.98,51.991 110.673,51.991 113.365,51.991 116.058,51.991 118.75,51.991 121.442,51.991 124.135,51.991 126.853,51.991 187.75,52 177.75,52.25 145.25,52.5 146.25,52.5 178.75,53 187.25,53 145,53.25 145.75,53.25 145.25,54 146.25,54 8.204,54.026 10.897,54.077 13.614,54.102 16.18,54.127 145,54.75 146,54.75 105.288,55.065 107.98,55.065 110.673,55.065 113.365,55.065 116.058,55.065 118.75,55.065 121.442,55.065 124.135,55.065 126.853,55.065 145.5,55.5 8.204,56.058 10.897,56.083 13.614,56.109 16.18,56.109 145,57.75 145.75,57.75 8.204,58.09 10.897,58.09 13.614,58.115 16.18,58.115 105.288,58.113 107.98,58.113 110.673,58.113 113.365,58.113 116.058,58.113 118.75,58.113 121.442,58.113 124.135,58.113 126.853,58.113 146.25,58.25 145,58.75 145.75,58.75 146.25,59.25 145,59.75 145.75,59.75 10.897,60.096 16.18,60.096 8.204,60.122 13.614,60.122 146,60.5 144.5,60.75 145.25,60.75 146,61.25 144.5,61.75 145.25,61.75 29.362,61.773 146,62 25.019,62.078 27.127,62.078 31.369,62.179 33.706,62.179 144.5,62.7 146,62.75 29.337,63.373 82.75,64.654 83.75,64.654 84.75,64.654 25.095,64.668 27.102,64.668 33.731,64.745 31.318,64.77 81.25,64.904 29.337,64.973 82.5,65.75 83.75,65.75 85,65.75 81.28,66.198 82.5,67 83.75,67 85,67 81.28,67.468 82.5,68.25 83.75,68.25 85,68.25 81.28,68.738 82.5,69.654 83.75,69.654 85,69.654 81.25,69.904 82.5,70.75 83.75,70.75 85,70.75 81.28,71.278 82.5,72 83.75,72 85,72 158.5,75.5 159.5,75.5 157.5,76.5 158.55,76.5 159.5,76.5 157.5,77.5 158.5,77.5 159.5,77.5 72,77.75 73.25,77.75 74.5,77.75 75.75,77.75 77,77.75 78.25,77.75 79.5,77.75 80.5,77.75 118.75,77.95 121.442,77.95 124.135,77.95 126.853,77.95 81.298,78 157.5,78.5 158.5,78.5 159.5,78.5 76.298,78.75 71.298,79 72.548,79 73.798,79 75.298,79 77.298,79 78.548,79 80.048,79 81.298,79 157.5,79.5 158.5,79.5 159.5,79.5 156.75,80 157.5,80.5 158.5,80.5 159.5,80.5 105.288,80.871 107.98,80.871 110.673,80.871 113.365,80.871 116.058,80.871 118.75,80.871 121.442,80.871 124.135,80.871 126.853,80.871 144.75,81.5 145.75,81.5 145.8,82.45 144.75,82.5 144.75,83.5 145.75,83.5 105.288,83.741 107.98,83.741 110.673,83.741 113.365,83.741 116.058,83.741 118.75,83.741 121.442,83.741 124.135,83.741 126.853,83.741 145,84.5 146,84.5 145,85.5 146,85.5 145,86.5 146,86.5 105.288,86.815 107.98,86.815 110.673,86.815 113.365,86.815 116.058,86.815 118.75,86.815 121.442,86.815 124.135,86.815 126.853,86.815 145.5,87.25 146,88.75 145.5,89.5 146.5,89.5 105.288,89.863 107.98,89.863 110.673,89.863 113.365,89.863 116.058,89.863 118.75,89.863 121.442,89.863 124.135,89.863 126.853,89.863 145.5,90.5 146.5,90.5 145.5,91.5 146.5,91.5 144.5,92.5 145.5,92.5 146.5,92.5 144.5,93.5 145.5,93.5 146.5,93.5 144.5,94.5 145.5,94.5 146.5,94.5 82.75,96.404 83.75,96.404 84.75,96.404 81.25,96.654 82.5,97.5 83.75,97.5 85,97.5 81.28,97.948 82.5,98.75 83.75,98.75 85,98.75 81.28,99.218 82.5,100 83.75,100 85,100 81.28,100.488 82.5,101.404 83.75,101.404 85,101.404 81.25,101.654 82.5,102.5 83.75,102.5 85,102.5 81.28,103.028 82.5,103.75 83.75,103.75 85,103.75 158,107.5 159,107.5 158,108.5 159,108.5 72,109.25 73.25,109.25 74.5,109.25 75.75,109.25 76.75,109.25 78.25,109.25 79.5,109.25 80.75,109.25 158,109.5 159,109.5 118.75,109.7 121.442,109.7 124.135,109.7 126.853,109.7 81.298,109.75 76.298,110.5 158,110.5 159,110.5 71.298,110.75 72.548,110.75 73.798,110.75 75.298,110.75 77.298,110.75 78.548,110.75 80.048,110.75 81.298,110.75 158,111.5 159,111.5 145.25,112.5 158,112.5 159,112.5 105.288,112.621 107.98,112.621 110.673,112.621 113.365,112.621 116.058,112.621 118.75,112.621 121.442,112.621 124.135,112.621 126.853,112.621 144.75,113.25 144.75,114.25 144.75,115.25 145.75,115.25 105.288,115.491 107.98,115.491 110.673,115.491 113.365,115.491 116.058,115.491 118.75,115.491 121.442,115.491 124.135,115.491 126.853,115.491 145,116.5 146,116.5 145,117.5 146,117.5 145,118.5 146,118.5 105.288,118.565 107.98,118.565 110.673,118.565 113.365,118.565 116.058,118.565 118.75,118.565 121.442,118.565 124.135,118.565 126.853,118.565 145,121.25 146.25,121.25 105.288,121.613 107.98,121.613 110.673,121.613 113.365,121.613 116.058,121.613 118.75,121.613 121.442,121.613 124.135,121.613 126.853,121.613 145.7,121.9 145,122.4 146,122.7 144.25,124 145,124.5 146,124.5 145.5,125.2 144.5,125.25 144.5,126.25 145.5,126.25 146.5,126.25
  other v2: 33.477,13.767 50.597,19.66 6.61,20.35 47.041,38.278 24.663,97.307 8.661,98.196 23.851,100.965 21.285,108.483 34.087,115.799 30.912,116.357 40.919,120.002
  other v5: 75.692,4.952 74.717,6.392 76.667,6.392 75.692,7.832 75.692,36.602 74.717,38.042 76.667,38.042 75.692,39.482 75.692,68.352 74.717,69.792 76.667,69.792 75.692,71.232 75.692,100.102 74.717,101.542 76.667,101.542 75.692,102.982
  other v6: 145.2,62.5 145.75,113.25 145.8,114.2 146.4,125.4
  other v7: 154.9,20.9 156.1,20.9 154.9,22.1 156.1,22.1 15.402,100.949 16.602,100.949 15.402,102.149 16.602,102.149
  other v9: 145,3.75
PH1_H: D13.2 Q16.4 R30.1 TP9.1 U4.3 | length 24.6
  Top Layer w0.5: U4.3@77.686,6.793 v3(78.807,6.793)
  MidLayer2 w0.5: TP9.1@70.25,9.85 71.75,9.85 72.4,9.2 76.4,9.2 ; v3(78.807,6.793) 78.705,6.793 77.621,7.877 77.621,7.979 76.4,9.2 ; v4(85,17.1) 85,14.1 82,11.1 78.7,11.1 76.8,9.2 76.4,9.2
PH1_L: D19.2 Q17.4 R39.2 TP14.1 U4.8 | length 19.6
  Top Layer w0.3: TP14.1@73.5,11.35 74.95,11.35 75.25,11.65 R39.2@76.25,11.65 ; v4(79.5,12.35) 79.525,12.325 Q17.4@80.4,12.325 81.625,12.325 D19.2@81.85,12.1
  Top Layer w0.5: v3(72.5,5.1) 72.593,5.193 U4.8@73.698,5.193
  Bottom Layer w0.5: v3(72.5,5.1) 73.5,6.1 TP14.1@73.5,11.35 74.5,12.35 v4(79.5,12.35)
PH2_H: D20.2 Q24.4 R53.1 TP21.1 U6.3 | length 25.9
  Top Layer w0.5: U6.3@77.686,38.443 v3@78.807,38.443
  MidLayer2 w0.5: TP21.1@70.25,41.5 71.75,41.5 72.6,40.65 75.85,40.65 ; v3(78.8,38.4) 78.179,39.021 77.856,39.021 76.226,40.65 75.85,40.65 ; v4(85,48.75) 85,45.75 81.95,42.7 76.7,42.7 75.85,41.85 75.85,40.65
PH2_L: D21.2 Q27.4 R59.2 TP27.1 U6.8 | length 19.6
  Top Layer w0.3: TP27.1@73.5,43 74.95,43 75.25,43.3 R59.2@76.25,43.3 ; v4(79.5,44) 79.525,43.975 Q27.4@80.4,43.975 81.625,43.975 D21.2@81.85,43.75
  Top Layer w0.5: v3(72.5,36.75) 72.593,36.843 U6.8@73.698,36.843
  Bottom Layer w0.5: v3(72.5,36.75) 73.5,37.75 TP27.1@73.5,43 74.5,44 v4(79.5,44)
PH3_H: D22.2 Q36.4 R72.1 TP37.1 U8.3 | length 24.2
  Top Layer w0.5: U8.3@77.686,70.193 v3@78.807,70.193
  MidLayer2 w0.5: TP37.1@70.25,73.25 71.75,73.25 72.375,72.625 77.5,72.625 ; v3(78.75,70.25) 78.548,70.25 77.521,71.277 77.521,71.479 77.5,71.5 77.5,72.625 ; v4(85,80.5) 85,77.5 82.1,74.6 79.475,74.6 77.5,72.625
PH3_L: D23.2 Q37.4 R78.2 TP40.1 U8.8 | length 19.6
  Top Layer w0.3: TP40.1@73.5,74.75 74.95,74.75 75.25,75.05 R78.2@76.25,75.05 ; v4(79.5,75.75) 79.525,75.725 Q37.4@80.4,75.725 81.625,75.725 D23.2@81.85,75.5
  Top Layer w0.5: v3(72.5,68.5) 72.593,68.593 U8.8@73.698,68.593
  Bottom Layer w0.5: v3(72.5,68.5) 73.5,69.5 TP40.1@73.5,74.75 74.5,75.75 v4(79.5,75.75)
PH4_H: D24.2 Q46.4 R91.1 TP47.1 U10.3 | length 24.3
  Top Layer w0.5: U10.3@77.686,101.943 v3@78.807,101.943
  MidLayer2 w0.5: TP47.1@70.25,105 71.8,105 72.707,104.093 77.621,104.093 ; v3(78.9,101.9) 78.379,102.421 78.077,102.421 77.621,102.877 77.621,104.093 ; 82.236,106.486 80.014,106.486 77.621,104.093 ; 82.25,106.5 85,109.25 v4(85,112.25)
PH4_L: D25.2 Q47.4 R97.2 TP51.1 U10.8 | length 19.6
  Top Layer w0.3: TP51.1@73.5,106.5 74.95,106.5 75.25,106.8 R97.2@76.25,106.8 ; v4(79.5,107.5) 79.525,107.475 Q47.4@80.4,107.475 81.625,107.475 D25.2@81.85,107.25
  Top Layer w0.5: v3(72.5,100.25) 72.593,100.343 U10.8@73.698,100.343
  Bottom Layer w0.5: v3(72.5,100.25) 73.5,101.25 TP51.1@73.5,106.5 74.5,107.5 v4(79.5,107.5)
PHASE1: C42.1 C54.1 D9.1 Q5.4 Q15.2 TP3.1 XF1.3 XF1.4 | length 43.6
  Top Layer w0.5: v3(133.7,18.4) 133.7,17.763 134.2,17.263 133.8,16.863 Q15.2@133.8,15.45
  Top Layer w1: Q5.4@93.218,25.044 Q5.4@93.218,26.018
  MidLayer2 w0.254: v1(97.75,21.5) 99.605,21.5 100,21.895 133.174,21.895 133.7,21.369 v3(133.7,18.4)
  other v1: 71.25,19.1 72.5,19.1 73.75,19.1 75,19.1 76.25,19.1 77.5,19.1 78.75,19.1 80,19.1 81.25,19.1 88,20 89.25,20 90.75,20 92,20 93,20 94,20 95.25,20 96.5,20 97.75,20 71.25,20.85 72.5,20.85 73.75,20.85 75,20.85 76.25,20.85 77.5,20.85 78.75,20.85 80,20.85 81.25,20.85 88,21.5 89.25,21.5 90.5,21.5 92,21.5 93,21.5 94,21.5 95.25,21.5 96.5,21.5
PHASE1_CBC: C59.1 R42.2 TP13.1 U3.7 | length 29.5
  Top Layer w0.254: TP13.1@22.809,3.404 24.613,5.207 24.613,10.113 v2(26.5,12) ; R42.2@24.981,20.803 v2(26.06,20.803) ; v2(29.934,21.615) 30.828,21.615 32.401,23.188 U3.7@33.76,23.188
  MidLayer2 w0.254: v2(26.5,12) 26.5,12.032 25.311,13.221 25.311,20.066 26.048,20.803 v2(26.06,20.803) 26.137,20.879 29.197,20.879 v2(29.934,21.615)
PHASE2: C64.1 C66.1 D11.1 Q18.4 Q25.2 XF3.3 XF3.4 | length 43.1
  Top Layer w0.254: Q25.2@134.05,60.45 D11.1@134.05,62.188 ; D11.1@134.113,62.25 v3(135.25,62.25)
  Top Layer w0.762: Q18.4@92.599,60.909 93.193,60.909 Q18.4@93.21,60.892
  MidLayer2 w0.254: v1(96.25,60.909) 97.622,62.281 v3@135.25,62.281
  other v1: 71.25,50.75 72.5,50.75 73.75,50.75 75,50.75 76.25,50.75 77.5,50.75 78.75,50.75 80,50.75 81.25,50.75 71.25,52.5 72.5,52.5 73.75,52.5 75,52.5 76.25,52.5 77.5,52.5 78.75,52.5 80,52.5 81.25,52.5 89.75,53 92.5,53 95.75,53 90.678,54.737 92.507,54.737 94.513,54.737 89,54.75 96.25,54.75 92.5,56 90.678,56.185 94.513,56.185 96.25,56.25 89,56.5 90.75,57.75 92.75,57.75 94.5,57.75 96.25,57.75 89,58 92.75,59.25 89,59.5 96.25,59.5 90.678,59.639 94.513,59.639 89,60.75 90.678,60.935 92.582,60.927 94.513,60.935
PHASE2_CBC: C68.1 R60.2 TP26.1 U3.6 | length 31.8
  Top Layer w0.254: v2(29.947,23.114) 30.861,23.114 31.435,23.688 U3.6@33.76,23.688
  MidLayer2 w0.254: v2(29.947,23.114) 29.159,22.327 v2(24.981,22.327) 24.803,22.149 24.803,12.491 26.398,10.897 33.477,10.897 33.909,10.465 TP26.1@33.909,7.874
PHASE3: C73.1 C75.1 D18.1 Q28.4 Q35.2 XF5.3 XF5.4 | length 43
  Top Layer w0.254: Q35.2@134.05,92.2 D18.1@134.05,93.938 ; D18.1@134.113,94 v3(135.25,94)
  Top Layer w0.762: Q28.4@92.599,92.659 93.193,92.659 Q28.4@93.21,92.642
  MidLayer2 w0.254: v1(96.25,92.659) 97.591,94 v3(135.25,94)
  other v1: 71.25,82.5 72.5,82.5 73.75,82.5 75,82.5 76.25,82.5 77.5,82.5 78.75,82.5 80,82.5 81.25,82.5 71.25,84.25 72.5,84.25 73.75,84.25 75,84.25 76.25,84.25 77.5,84.25 78.75,84.25 80,84.25 81.25,84.25 89.75,84.75 92.5,84.75 95.75,84.75 90.678,86.487 92.507,86.487 94.513,86.487 89,86.5 96.25,86.5 92.5,87.75 90.678,87.935 94.513,87.935 96.25,88 89,88.25 90.75,89.5 92.75,89.5 94.5,89.5 96.25,89.5 89,89.75 92.75,91 89,91.25 96.25,91.25 90.678,91.389 94.513,91.389 89,92.5 90.678,92.685 92.582,92.677 94.513,92.685
PHASE3_CBC: C77.1 R79.2 TP39.1 U3.4 | length 39.1
  Top Layer w0.254: v2(29.947,26.162) 31.413,24.696 32.208,24.696 ; 32.208,24.688 U3.4@33.76,24.688
  MidLayer2 w0.254: v2(29.947,26.162) 29.083,25.298 24.994,25.298 v2(24.968,25.324) 24.295,24.651 24.295,12.281 26.187,10.389 31.572,10.389 32.08,9.881 32.08,5.232 TP39.1@33.909,3.404
PHASE4: C82.1 C84.1 D15.1 Q38.4 Q45.2 XF7.3 XF7.4 | length 53.6
  Top Layer w0.254: Q45.2@134.05,123.95 D15.1@134.05,125.688 ; D15.1@134.113,125.75 134.362,126 v3(135.3,126)
  Top Layer w0.762: Q38.4@92.599,124.409 93.193,124.409 Q38.4@93.21,124.392
  MidLayer2 w0.254: v4(86,125.5) 86.75,126.25 87.184,126.25 87.438,126.504 134.062,126.504 134.316,126.25 134.75,126.25 135,126 v3(135.3,126)
  other v1: 71.25,114.25 72.5,114.25 73.75,114.25 75,114.25 76.25,114.25 77.5,114.25 78.75,114.25 80,114.25 81.25,114.25 71.25,116 72.5,116 73.75,116 75,116 76.25,116 77.5,116 78.75,116 80,116 81.25,116 89.75,116.5 92.5,116.5 95.75,116.5 90.678,118.237 92.507,118.237 94.513,118.237 89,118.25 96.25,118.25 92.5,119.5 90.678,119.685 94.513,119.685 96.25,119.75 89,120 90.75,121.25 92.75,121.25 94.5,121.25 96.25,121.25 89,121.5 92.75,122.75 94.5,122.75 89,123 96.25,123 90.678,123.139 89.75,124 91.25,124 93,124 94.75,124 97,124
PHASE4_CBC: C86.1 R98.2 TP50.1 U3.1 | length 41.2
  Top Layer w0.254: v2(29.947,29.108) 30.734,29.108 31.081,28.762 31.081,28.058 32.92,26.219 U3.1@33.76,26.219
  MidLayer2 w0.254: v2(29.947,29.108) 29.159,28.321 25.019,28.321 v2(24.968,28.27) 23.787,28.27 23.279,27.762 23.279,11.86 25.767,9.373 27.915,9.373 28.372,8.915 28.372,5.283 TP50.1@30.251,3.404
PMBUS_ALERT: R24.2 U3.17 | length 35.6
  Top Layer w0.254: v2(32.182,16.18) 32.182,17.781 32.588,18.188 U3.17@33.76,18.188
  Bottom Layer w0.254: v2(3.231,18.762) 4.894,17.1 11.241,17.1 13.988,19.847 16.053,19.847 19.15,16.75 19.428,16.75 19.584,16.594 24.193,16.594 24.607,16.18 v2(32.182,16.18)
PMBUS_CLK: R14.2 U3.15 | length 25.3
  Top Layer w0.254: v2(32.36,19.202) 32.374,19.188 U3.15@33.76,19.188
  Bottom Layer w0.254: v2(11.448,20.426) 12.622,21.6 16.5,21.6 20.1,18 25.053,18 25.349,17.704 31.299,17.704 32.36,18.764 v2(32.36,19.202)
PMBUS_CTRL: R26.2 U3.18 | length 36.1
  Top Layer w0.254: U3.18@33.76,17.688 35.341,17.688 v2(35.535,17.882)
  Bottom Layer w0.254: v2(4.781,18.762) 5.843,17.7 11.2,17.7 13.8,20.3 16.5,20.3 19.55,17.25 19.569,17.25 19.772,17.047 24.49,17.047 24.849,16.688 31.72,16.688 32.914,17.882 v2(35.535,17.882)
PMBUS_DATA: R13.2 U3.16 | length 29.2
  Top Layer w0.254: U3.16@33.76,18.688 35.147,18.688 v2(35.56,19.101)
  Bottom Layer w0.254: v2(11.423,18.826) 13.397,20.8 16.659,20.8 19.959,17.5 24.75,17.5 25.054,17.196 31.51,17.196 32.703,18.39 34.849,18.39 v2(35.56,19.101)
PWM0: U3.39 U14.3 | length 6.2
  Top Layer w0.254: U3.39@44.56,14.888 44.56,13.708 45.034,13.233 47.219,13.233 48.065,14.08 U14.3@49.019,14.08
PWM1: U3.40 U14.1 | length 5.5
  Top Layer w0.254: U3.40@45.06,14.888 45.06,13.944 45.263,13.741 46.99,13.741 48.328,15.08 U14.1@49.019,15.08
SAFTY_SW1: C107.1 Q12.1 R124.1 TP10.1 | length 5.6
  Top Layer w0.5: R124.1@138.95,19.75 138.95,18.65 C107.1@138.8,18.5 ; Q12.1@139.2,16.95 139.2,18.1 C107.1@138.8,18.5 ; TP10.1@141.25,18.75 141,18.5 C107.1@138.8,18.5
SAFTY_SW2: C111.1 Q23.1 R125.1 TP25.1 | length 6.9
  Top Layer w0.254: Q23.1@145.638,38.8 145.638,37.324 C111.1@145.75,37.212 ; C111.1@145.788,37.25 C111.1@145.75,37.212 ; TP25.1@148.25,34.5 146.05,34.5 R125.1@145.75,34.8 145.5,35.05 145.5,36 145.5,36.962 C111.1@145.75,37.212
SAFTY_SW3: C110.1 Q34.1 R126.1 TP38.1 | length 8.2
  Top Layer w0.254: C110.1@145.638,69.074 Q34.1@145.638,70.55 ; R126.1@145.75,67.05 R126.1@145.788,67.012 ; C110.1@145.788,69 R126.1@145.788,67.012 ; R126.1@145.788,67.012 146.25,66.55 ; 146.25,66.55 148.2,66.55 TP38.1@148.25,66.5 146.3,66.5 146.25,66.55
SAFTY_SW4: C113.1 Q43.1 R127.1 TP49.1 | length 6.9
  Top Layer w0.254: Q43.1@145.638,102.3 145.638,100.824 C113.1@145.75,100.712 ; C113.1@145.788,100.75 C113.1@145.75,100.712 ; TP49.1@148.25,98 146.05,98 R127.1@145.75,98.3 145.5,98.55 145.5,99.5 145.5,100.462 C113.1@145.75,100.712
SW1: C60.2 L3.1 Q5.2 Q5.3 Q5.5 Q5.6 Q5.7 Q6.4 Q16.5 Q16.6 Q16.7 Q16.8 R30.2 TP4.1 U4.4 | length 15.8
  Top Layer w0.254: Q5.2@90.371,14.895 Q5.2@90.399,14.922
  Top Layer w0.508: U4.4@77.686,7.593 77.793,7.593 v3(78.4,8.2) ; v3@78.588,8.112 C60.2@80,8.112 ; Q6.4@88.659,8.115 Q6.4@89.408,7.366
  MidLayer2 w0.508: v3(78.4,8.2) 78.4,9 79.547,10.147 89.167,10.147 v1(89.383,9.931)
  other v1: 89.525,3.056 90.745,3.056 93.525,3.056 94.745,3.056 91.989,3.082 95.989,3.082 109,3.258 109.991,3.258 110.981,3.258 111.972,3.258 112.962,3.258 89.5,4.25 90.77,4.25 91.989,4.25 93.5,4.25 94.77,4.25 95.989,4.25 109,4.706 109.991,4.706 110.981,4.706 112.962,4.706 112,4.758 89.475,5.368 90.745,5.368 91.989,5.368 93.475,5.368 94.745,5.368 95.989,5.368 109,6.078 109.991,6.078 110.981,6.078 111.972,6.078 112.962,6.078 89.383,7.366 90.703,7.366 91.948,7.366 93.599,7.366 94.818,7.366 96.063,7.391 109,7.5 109.991,7.5 110.981,7.5 111.972,7.5 112.962,7.5 93.574,8.56 94.844,8.56 96.063,8.56 89.383,8.611 90.678,8.611 91.923,8.611 93.548,9.677 94.818,9.677 96.063,9.677 90.653,9.931 91.923,9.931 90.424,13.208 93.447,13.233 96.495,13.233 91.948,13.462 94.971,13.487 97.765,13.741 90.75,14.75 92,14.75 93.25,14.75 94.5,14.75 95.75,14.75 97,14.75 98.25,14.75 90.75,16 92,16 93.25,16 94.5,16 95.75,16 97,16 98.25,16.25 90.75,17.25 92,17.25 93.25,17.25 94.5,17.25 95.75,17.25 97,17.25
SW2: C69.2 L4.1 Q18.2 Q18.3 Q18.5 Q18.6 Q18.7 Q22.4 Q24.5 Q24.6 Q24.7 Q24.8 R53.2 TP22.1 U6.4 | length 17.5
  Top Layer w0.254: Q18.2@90.274,46.822 Q18.2@90.373,46.723 ; L4.1@111.883,36.72 L4.1@112.849,35.754
  Top Layer w0.508: U6.4@77.686,39.243 78.019,39.243 78.438,39.662 C69.2@80,39.662 ; L4.1@110.993,37.609 L4.1@111.883,36.72 ; L4.1@111.049,35.763 L4.1@113.284,35.763 ; L4.1@112.849,35.754 L4.1@113,35.754
  MidLayer2 w0.508: v3@78.2,39.9 78.2,40.45 79.547,41.797 86.953,41.797
  other v1: 88.25,33.5 89.5,33.5 90.75,33.5 92,33.5 93.5,33.5 95,33.5 96.5,33.5 88.25,35.25 89.5,35.25 90.75,35.25 92,35.25 93.5,35.25 95,35.25 96.5,35.25 109.038,35.5 110.028,35.5 111.019,35.5 112.009,35.5 113,35.5 110.993,36.821 111.984,36.821 109.038,36.846 110.028,36.846 113,36.846 88.25,37 89.5,37 90.75,37 92,37 93.5,37 95,37 96.5,37 109.038,38.218 110.028,38.218 111.019,38.218 112.009,38.218 113,38.218 88.25,38.75 89.5,38.75 90.75,38.75 92,38.75 93.5,38.75 95,38.75 96.5,38.75 109.038,39.666 110.028,39.666 111.019,39.666 112.009,39.666 113,39.666 88.25,40.5 89.5,40.5 90.75,40.5 92,40.5 93.5,40.5 95,40.5 96.5,40.5 90.5,44.25 91.75,44.25 93,44.25 94.25,44.25 95.75,44.25 97.25,44.25 98.25,44.25 90.25,45.5 91.5,45.5 92.75,45.5 94,45.5 95.5,45.5 97,45.5 98,45.5 90.75,46.75 92,46.75 93.25,46.75 94.5,46.75 95.75,46.75 97,46.75 98,46.75 93.25,48 90.678,48.086 91.948,48.086 94.488,48.086 95.758,48.086 97.028,48.086 98,48.25 93.25,49 90.75,49.25 92,49.25 94.5,49.25 95.75,49.25 97,49.25
  other v3: 78.5,39.8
